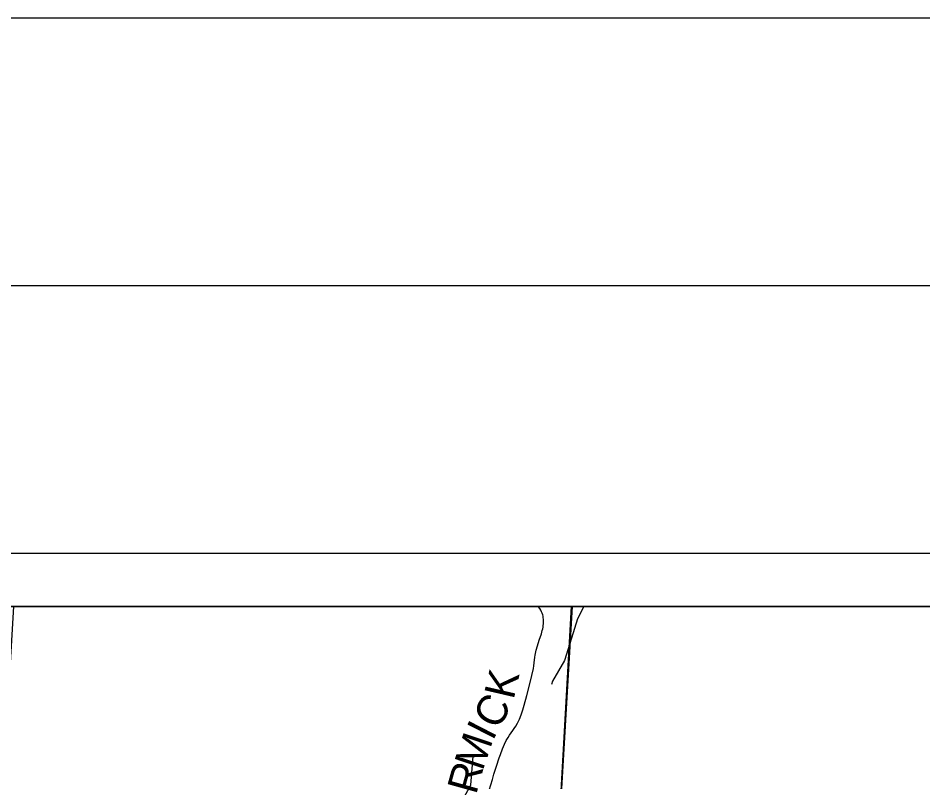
# Model space of a CAD drawing. Extents: x 0 to 34, y 0 to 22.
# Drawn here: x 5.267 to 6.959, y 20.572 to 22 of the extents above; entities that cross this region are included whole.
import ezdxf

# ---------------------------------------------------------------- set-up
doc = ezdxf.new("R2010")
doc.units = 0
for name, color, linetype in [('Default', 7, 'Continuous'), ('GM_X_County_Road', 7, 'Continuous'), ('GM_X_County_Road_Text', 7, 'Continuous'), ('GM_X_Minor_River', 7, 'Continuous'), ('SH_Border', 7, 'Continuous'), ('SH_Cut_Line', 7, 'Continuous'), ('SH_Data', 7, 'Continuous'), ('SH_Text', 7, 'Continuous')]:
    doc.layers.add(name, color=color, linetype=linetype)

msp = doc.modelspace()

# ---------------------------------------------------------------- linework, layer by layer
at = {"layer": 'Default'}
for points in [[(6.0603, 16.8624), (6.127, 17.9511), (6.1612, 18.4732), (6.1665, 18.5542), (6.1773, 18.7192), (6.1898, 18.9313), (6.195, 19.011), (6.2406, 19.7849), (6.241, 19.7927), (6.2413, 19.8018), (6.2418, 19.8127), (6.2424, 19.8289), (6.2426, 19.8432), (6.2426, 19.8474), (6.2427, 19.8586), (6.2428, 19.8591), (6.2428, 19.8627), (6.2428, 19.867), (6.2428, 19.8705), (6.2431, 19.8748), (6.2438, 19.8792), (6.3032, 20.9), (2.1, 20.9), (2.1, 16.1239)], [(8.9, 20.9), (6.3032, 20.9), (6.2438, 19.8792), (6.2431, 19.8748), (6.2428, 19.8705), (6.2428, 19.867), (6.2428, 19.8627), (6.2428, 19.8591), (6.2427, 19.8586), (6.2426, 19.8474), (6.2426, 19.8432), (6.2424, 19.8289), (6.2418, 19.8127), (6.2413, 19.8018), (6.241, 19.7927), (6.2406, 19.7849), (6.195, 19.011), (6.1898, 18.9313), (6.1773, 18.7192), (6.1665, 18.5542), (6.1612, 18.4732), (6.127, 17.9511), (6.0603, 16.8624)]]:
    msp.add_lwpolyline(points, dxfattribs=at)
for points in [[(6.302, 20.9), (5.259, 20.9), (5.2086, 20.056), (6.2522, 20.0112)], [(7.3433, 20.9), (6.302, 20.9), (6.2522, 20.0112), (7.2788, 19.9659)]]:
    msp.add_lwpolyline(points, close=True, dxfattribs=at)
at = {"layer": 'GM_X_County_Road'}
msp.add_lwpolyline([(6.1484, 20.5572), (6.1543, 20.5772), (6.1572, 20.5869), (6.1619, 20.6018), (6.1671, 20.6175), (6.1691, 20.6234), (6.1732, 20.6345), (6.1769, 20.6429), (6.1802, 20.6496), (6.1835, 20.6554), (6.1864, 20.66), (6.1892, 20.6642), (6.1924, 20.6683), (6.1952, 20.672), (6.1982, 20.6769), (6.2011, 20.6823), (6.2047, 20.69), (6.2079, 20.698), (6.2111, 20.7071), (6.2139, 20.716), (6.2188, 20.7337), (6.2251, 20.7585), (6.2309, 20.7844), (6.2318, 20.7896), (6.2326, 20.7947), (6.2338, 20.8058), (6.2342, 20.8093), (6.2347, 20.8125), (6.2353, 20.8155), (6.236, 20.8185), (6.2386, 20.827), (6.242, 20.8374), (6.2459, 20.8494), (6.2476, 20.8553), (6.2484, 20.8586), (6.249, 20.8616), (6.2493, 20.8648), (6.2496, 20.8676), (6.2498, 20.8707), (6.2498, 20.8733), (6.2497, 20.8765), (6.2494, 20.8794), (6.249, 20.8821), (6.2484, 20.8846), (6.2473, 20.8878), (6.2463, 20.8906), (6.245, 20.8935), (6.2429, 20.8967), (6.2406, 20.8997), (6.2403, 20.9)], dxfattribs=at)
at = {"layer": 'GM_X_Minor_River'}
for points in [[(6.325, 20.9), (6.3131, 20.8773), (6.3021, 20.8411), (6.2888, 20.7993), (6.2668, 20.7605), (6.2645, 20.7544)], [(6.2282, 19.712), (6.2097, 19.8916), (6.1471, 19.9191), (6.1042, 19.9787), (6.1033, 20.0436), (6.1202, 20.1158), (6.1124, 20.2467), (6.1114, 20.4376), (6.0824, 20.5098), (6.1139, 20.5663), (6.1185, 20.6206)]]:
    msp.add_lwpolyline(points, dxfattribs=at)
at = {"layer": 'SH_Border'}
msp.add_lwpolyline([(1.5, 21.5), (33.5, 21.5), (33.5, 0.5), (1.5, 0.5)], close=True, dxfattribs=at)
at = {"layer": 'SH_Cut_Line'}
msp.add_lwpolyline([(0, 0), (34, 0), (34, 22), (0, 22)], close=True, dxfattribs=at)
at = {"layer": 'SH_Data'}
for p, q in [((2, 21), (9, 21)), ((2.1, 20.9), (8.9, 20.9))]:
    msp.add_line(p, q, dxfattribs=at)
at = {"layer": 'SH_Text'}
msp.add_lwpolyline([(8.9, 20.9), (2.1, 20.9)], dxfattribs=at)

# ---------------------------------------------------------------- texts
at = {"layer": 'GM_X_County_Road_Text'}
for s, rotation, p in [('K', 76.9123, (6.1938, 20.7248)), ('C', 61.2195, (6.1652, 20.6681)), ('I', 62.8345, (6.1548, 20.6477)), ('M', 71.3577, (6.1359, 20.5913)), ('R', 74.4803, (6.1237, 20.5472))]:
    msp.add_text(s, height=0.0568, rotation=rotation, dxfattribs=at).set_placement(p)

doc.saveas('drawing.dxf')
